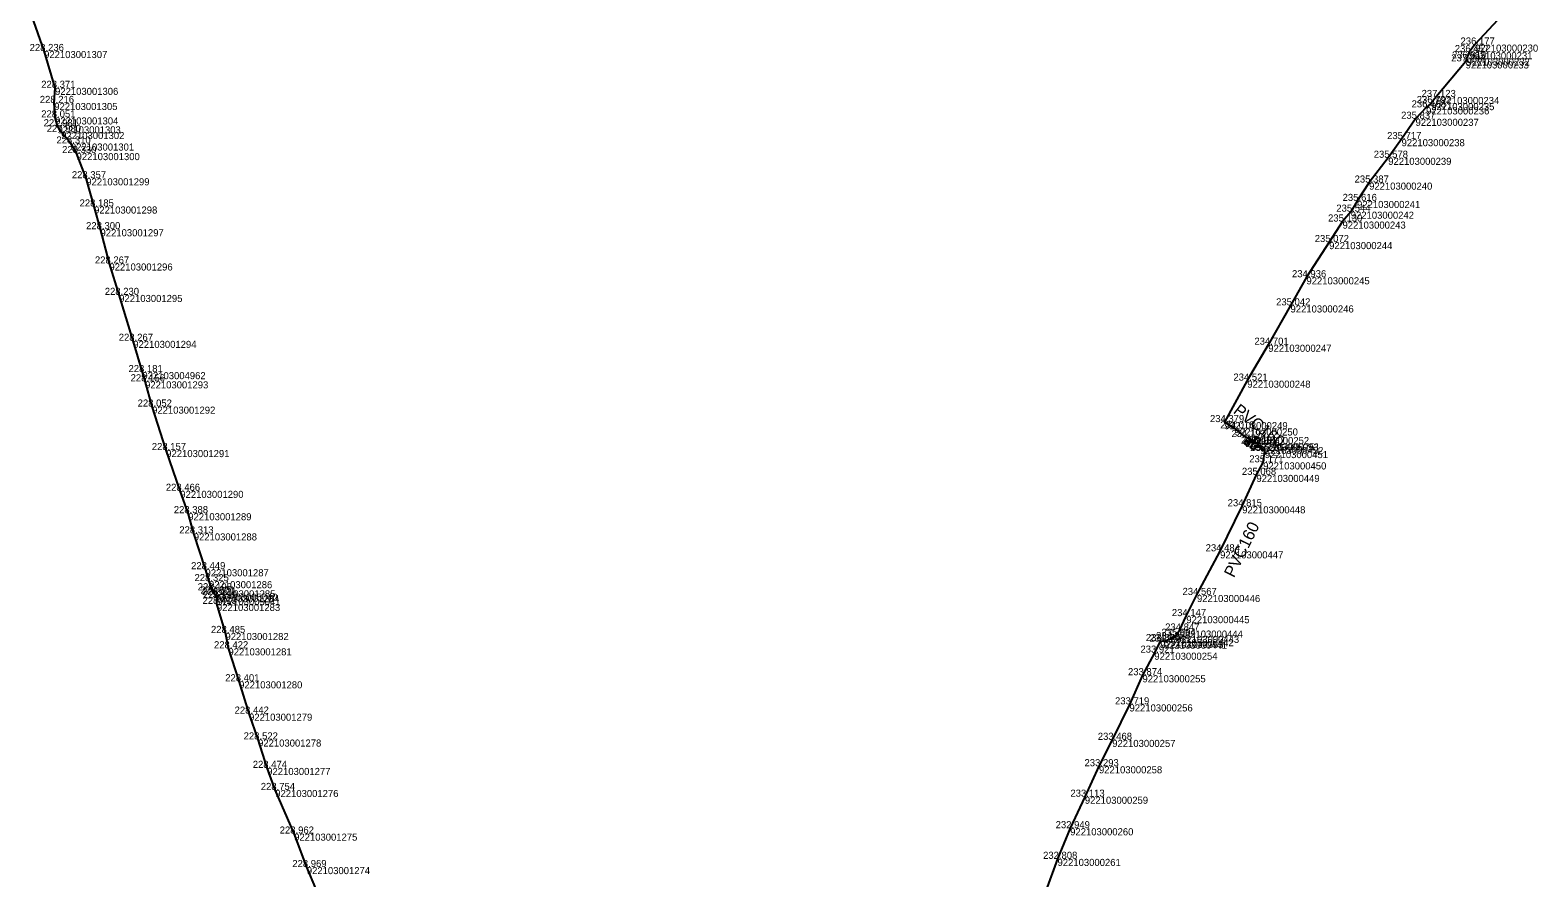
# Model space of a CAD drawing. Extents: x -771047 to -756200, y -1053876 to -1046520.
# Drawn here: x -768886.3 to -768630.8, y -1052633.5 to -1052489.9 of the extents above; entities that cross this region are included whole.
import ezdxf

# ---------------------------------------------------------------- set-up
doc = ezdxf.new("R2010")
doc.units = 0
for name, color, linetype in [('Vrstva 32', 7, 'Continuous'), ('Vrstva 33', 7, 'Continuous'), ('Vrstva 60', 7, 'Continuous'), ('Vrstva 61', 7, 'Continuous')]:
    doc.layers.add(name, color=color, linetype=linetype)

msp = doc.modelspace()

# ---------------------------------------------------------------- linework, layer by layer
at = {"layer": 'Vrstva 32'}
for points in [[(-768859.48, -1052571.73), (-768860.83, -1052567.94), (-768863.21, -1052561.03), (-768865.61, -1052553.67), (-768866.8, -1052549.39), (-768867.25, -1052547.83), (-768868.8, -1052542.53), (-768871.18, -1052534.75), (-768872.84, -1052529.43), (-768874.35, -1052523.62), (-768875.44, -1052519.77), (-768876.76, -1052514.99), (-768878.41, -1052510.72), (-768879.37, -1052509.1), (-768881.02, -1052507.15), (-768881.63, -1052506.19), (-768882.04, -1052504.68), (-768882.19, -1052502.23), (-768882.05, -1052499.67), (-768883.91, -1052493.43), (-768886.01, -1052487.46)], [(-768636.76, -1052487.33), (-768641.43, -1052492.34), (-768642.4, -1052493.62), (-768642.86, -1052494.7), (-768643.01, -1052495.19), (-768648.03, -1052501.22), (-768648.85, -1052502.25), (-768649.71, -1052502.98), (-768651.5, -1052504.91), (-768653.87, -1052508.36), (-768656.13, -1052511.52), (-768659.37, -1052515.72), (-768661.41, -1052518.83), (-768662.48, -1052520.65), (-768663.88, -1052522.32), (-768666.14, -1052525.8), (-768669.99, -1052531.76), (-768672.69, -1052536.53), (-768676.46, -1052543.19), (-768680.01, -1052549.27), (-768683.89, -1052556.3)], [(-768691.48, -1052591.61), (-768690.35, -1052589.17), (-768688.54, -1052585.58), (-768684.62, -1052578.19), (-768680.88, -1052570.56), (-768678.47, -1052565.24), (-768677.33, -1052563.12), (-768677.05, -1052561.2), (-768677.83, -1052560.51), (-768678.45, -1052559.88), (-768680.25, -1052558.83), (-768682.15, -1052557.37), (-768683.89, -1052556.3)], [(-768855.96, -1052583.24), (-768856.55, -1052581.22), (-768858.55, -1052575.15), (-768859.48, -1052571.73)], [(-768846.1, -1052614.88), (-768847.65, -1052610.06), (-768849.18, -1052605.69), (-768850.86, -1052600.21), (-768852.67, -1052594.62), (-768853.18, -1052592.02), (-768854.62, -1052587.1), (-768854.56, -1052586.13), (-768854.77, -1052585.61), (-768855.05, -1052585.35), (-768855.43, -1052584.79), (-768855.96, -1052583.24)], [(-768691.48, -1052591.61), (-768692.11, -1052592.5), (-768693.03, -1052593.06), (-768694.16, -1052593.48), (-768694.77, -1052593.39), (-768695.77, -1052595.36), (-768697.78, -1052599.18), (-768699.98, -1052604.12), (-768702.9, -1052610.13), (-768705.15, -1052614.6), (-768707.54, -1052619.76), (-768710.03, -1052625.1), (-768712.17, -1052630.29), (-768714.18, -1052635.7), (-768715.9, -1052640.84), (-768716.73, -1052643.85)], [(-768836.1, -1052638.7), (-768836.79, -1052637.16), (-768837.87, -1052635.33), (-768839.39, -1052631.68), (-768841.54, -1052626.01), (-768844.74, -1052618.62), (-768846.1, -1052614.88)]]:
    msp.add_lwpolyline(points, dxfattribs=at)
at = {"layer": 'Vrstva 33'}
for points in [[(-768678.45, -1052559.88), (-768680.25, -1052558.83), (-768682.15, -1052557.37), (-768683.89, -1052556.3)], [(-768680.37, -1052560.05), (-768680.47, -1052559.93), (-768680.46, -1052559.69), (-768680.4, -1052559.6), (-768680.2, -1052559.48), (-768680.04, -1052559.52)], [(-768680.04, -1052559.52), (-768679.6, -1052559.8)], [(-768679.27, -1052559.26), (-768679.92, -1052560.33)], [(-768679.92, -1052560.33), (-768680.37, -1052560.05)], [(-768690.35, -1052589.17), (-768688.54, -1052585.58), (-768684.62, -1052578.19), (-768680.88, -1052570.56), (-768678.47, -1052565.24), (-768677.33, -1052563.12)]]:
    msp.add_lwpolyline(points, dxfattribs=at)
msp.add_lwpolyline([(-768678.84, -1052560.98), (-768679.47, -1052560.59), (-768678.42, -1052558.88), (-768677.79, -1052559.27)], close=True, dxfattribs=at)
at = {"layer": 'Vrstva 60'}
for p, q in [((-768641.43, -1052492.34), (-768641.43, -1052492.34)), ((-768883.91, -1052493.43), (-768883.91, -1052493.43)), ((-768643.01, -1052495.19), (-768643.01, -1052495.19)), ((-768642.86, -1052494.7), (-768642.86, -1052494.7)), ((-768642.4, -1052493.62), (-768642.4, -1052493.62)), ((-768882.05, -1052499.67), (-768882.05, -1052499.67)), ((-768882.19, -1052502.23), (-768882.19, -1052502.23)), ((-768649.71, -1052502.98), (-768649.71, -1052502.98)), ((-768648.85, -1052502.25), (-768648.85, -1052502.25)), ((-768648.03, -1052501.22), (-768648.03, -1052501.22)), ((-768882.04, -1052504.68), (-768882.04, -1052504.68)), ((-768651.5, -1052504.91), (-768651.5, -1052504.91)), ((-768881.63, -1052506.19), (-768881.63, -1052506.19)), ((-768881.02, -1052507.15), (-768881.02, -1052507.15)), ((-768653.87, -1052508.36), (-768653.87, -1052508.36)), ((-768879.37, -1052509.1), (-768879.37, -1052509.1)), ((-768878.41, -1052510.72), (-768878.41, -1052510.72)), ((-768656.13, -1052511.52), (-768656.13, -1052511.52)), ((-768876.76, -1052514.99), (-768876.76, -1052514.99)), ((-768659.37, -1052515.72), (-768659.37, -1052515.72)), ((-768661.41, -1052518.83), (-768661.41, -1052518.83)), ((-768875.44, -1052519.77), (-768875.44, -1052519.77)), ((-768662.48, -1052520.65), (-768662.48, -1052520.65)), ((-768874.35, -1052523.62), (-768874.35, -1052523.62)), ((-768663.88, -1052522.32), (-768663.88, -1052522.32)), ((-768666.14, -1052525.8), (-768666.14, -1052525.8)), ((-768872.84, -1052529.43), (-768872.84, -1052529.43)), ((-768669.99, -1052531.76), (-768669.99, -1052531.76)), ((-768871.18, -1052534.75), (-768871.18, -1052534.75)), ((-768672.69, -1052536.53), (-768672.69, -1052536.53)), ((-768868.8, -1052542.53), (-768868.8, -1052542.53)), ((-768676.46, -1052543.19), (-768676.46, -1052543.19)), ((-768867.25, -1052547.83), (-768867.25, -1052547.83)), ((-768866.8, -1052549.39), (-768866.8, -1052549.39)), ((-768680.01, -1052549.27), (-768680.01, -1052549.27)), ((-768865.61, -1052553.67), (-768865.61, -1052553.67)), ((-768683.89, -1052556.3), (-768683.89, -1052556.3)), ((-768682.15, -1052557.37), (-768682.15, -1052557.37)), ((-768680.25, -1052558.83), (-768680.25, -1052558.83)), ((-768863.21, -1052561.03), (-768863.21, -1052561.03)), ((-768678.63, -1052559.93), (-768678.63, -1052559.93)), ((-768678.45, -1052559.88), (-768678.45, -1052559.88)), ((-768677.83, -1052560.51), (-768677.83, -1052560.51)), ((-768677.05, -1052561.2), (-768677.05, -1052561.2)), ((-768677.33, -1052563.12), (-768677.33, -1052563.12)), ((-768678.47, -1052565.24), (-768678.47, -1052565.24)), ((-768860.83, -1052567.94), (-768860.83, -1052567.94)), ((-768859.48, -1052571.73), (-768859.48, -1052571.73)), ((-768680.88, -1052570.56), (-768680.88, -1052570.56)), ((-768858.55, -1052575.15), (-768858.55, -1052575.15)), ((-768684.62, -1052578.19), (-768684.62, -1052578.19)), ((-768856.55, -1052581.22), (-768856.55, -1052581.22)), ((-768855.96, -1052583.24), (-768855.96, -1052583.24)), ((-768855.43, -1052584.79), (-768855.43, -1052584.79)), ((-768855.05, -1052585.35), (-768855.05, -1052585.35)), ((-768854.77, -1052585.61), (-768854.77, -1052585.61)), ((-768854.62, -1052587.1), (-768854.62, -1052587.1)), ((-768854.56, -1052586.13), (-768854.56, -1052586.13)), ((-768688.54, -1052585.58), (-768688.54, -1052585.58)), ((-768690.35, -1052589.17), (-768690.35, -1052589.17)), ((-768853.18, -1052592.02), (-768853.18, -1052592.02)), ((-768692.11, -1052592.5), (-768692.11, -1052592.5)), ((-768691.48, -1052591.61), (-768691.48, -1052591.61)), ((-768852.67, -1052594.62), (-768852.67, -1052594.62)), ((-768695.77, -1052595.36), (-768695.77, -1052595.36)), ((-768694.77, -1052593.39), (-768694.77, -1052593.39)), ((-768694.16, -1052593.48), (-768694.16, -1052593.48)), ((-768693.03, -1052593.06), (-768693.03, -1052593.06)), ((-768850.86, -1052600.21), (-768850.86, -1052600.21)), ((-768697.78, -1052599.18), (-768697.78, -1052599.18)), ((-768849.18, -1052605.69), (-768849.18, -1052605.69)), ((-768699.98, -1052604.12), (-768699.98, -1052604.12)), ((-768847.65, -1052610.06), (-768847.65, -1052610.06)), ((-768702.9, -1052610.13), (-768702.9, -1052610.13)), ((-768846.1, -1052614.88), (-768846.1, -1052614.88)), ((-768705.15, -1052614.6), (-768705.15, -1052614.6)), ((-768844.74, -1052618.62), (-768844.74, -1052618.62)), ((-768707.54, -1052619.76), (-768707.54, -1052619.76)), ((-768841.54, -1052626.01), (-768841.54, -1052626.01)), ((-768710.03, -1052625.1), (-768710.03, -1052625.1)), ((-768712.17, -1052630.29), (-768712.17, -1052630.29)), ((-768839.39, -1052631.68), (-768839.39, -1052631.68))]:
    msp.add_line(p, q, dxfattribs=at)

# ---------------------------------------------------------------- texts
at = {"layer": 'Vrstva 33'}
for rotation, p in [(322.2959, (-768682.52, -1052554.64)), (63.899, (-768682.27, -1052582.78))]:
    msp.add_text('PVC160', height=2, rotation=rotation, dxfattribs=at).set_placement(p)
at = {"layer": 'Vrstva 60'}
for s, p in [('922103000230', (-768641.43, -1052493.54)), ('922103001307', (-768883.91, -1052494.63)), ('922103000233', (-768643.01, -1052496.39)), ('922103000232', (-768642.86, -1052495.9)), ('922103000231', (-768642.4, -1052494.82)), ('922103001306', (-768882.05, -1052500.87)), ('922103001305', (-768882.19, -1052503.43)), ('922103000236', (-768649.71, -1052504.18)), ('922103000235', (-768648.85, -1052503.45)), ('922103000234', (-768648.03, -1052502.42)), ('922103001304', (-768882.04, -1052505.88)), ('922103000237', (-768651.5, -1052506.11)), ('922103001303', (-768881.63, -1052507.39)), ('922103001302', (-768881.02, -1052508.35)), ('922103000238', (-768653.87, -1052509.56)), ('922103001301', (-768879.37, -1052510.3)), ('922103001300', (-768878.41, -1052511.92)), ('922103000239', (-768656.13, -1052512.72)), ('922103001299', (-768876.76, -1052516.19)), ('922103000240', (-768659.37, -1052516.92)), ('922103000241', (-768661.41, -1052520.03)), ('922103001298', (-768875.44, -1052520.97)), ('922103000242', (-768662.48, -1052521.85)), ('922103001297', (-768874.35, -1052524.82)), ('922103000243', (-768663.88, -1052523.52)), ('922103000244', (-768666.14, -1052527)), ('922103001296', (-768872.84, -1052530.62)), ('922103000245', (-768669.99, -1052532.96)), ('922103001295', (-768871.18, -1052535.95)), ('922103000246', (-768672.69, -1052537.73)), ('922103001294', (-768868.8, -1052543.73)), ('922103000247', (-768676.46, -1052544.39)), ('922103004962', (-768867.25, -1052549.03)), ('922103001293', (-768866.8, -1052550.59)), ('922103000248', (-768680.01, -1052550.47)), ('922103001292', (-768865.61, -1052554.87)), ('922103000249', (-768683.89, -1052557.5)), ('922103000250', (-768682.15, -1052558.57)), ('922103000252', (-768680.25, -1052560.03)), ('922103001291', (-768863.21, -1052562.23)), ('922103005093', (-768678.63, -1052561.13)), ('922103000251', (-768678.45, -1052561.08)), ('922103000452', (-768677.83, -1052561.71)), ('922103000451', (-768677.05, -1052562.4)), ('922103000450', (-768677.33, -1052564.32)), ('922103000449', (-768678.47, -1052566.44)), ('922103001290', (-768860.83, -1052569.14)), ('922103001289', (-768859.48, -1052572.93)), ('922103000448', (-768680.88, -1052571.76)), ('922103001288', (-768858.55, -1052576.35)), ('922103000447', (-768684.62, -1052579.39)), ('922103001287', (-768856.55, -1052582.42)), ('922103001286', (-768855.96, -1052584.44)), ('922103001285', (-768855.43, -1052585.99)), ('922103005040', (-768855.05, -1052586.55)), ('922103001284', (-768854.77, -1052586.81)), ('922103001283', (-768854.62, -1052588.3)), ('922103005041', (-768854.56, -1052587.33)), ('922103000446', (-768688.54, -1052586.78)), ('922103000445', (-768690.35, -1052590.37)), ('922103001282', (-768853.18, -1052593.22)), ('922103000443', (-768692.11, -1052593.7)), ('922103000444', (-768691.48, -1052592.81)), ('922103001281', (-768852.67, -1052595.82)), ('922103000254', (-768695.77, -1052596.56)), ('922103000253', (-768694.77, -1052594.59)), ('922103000441', (-768694.16, -1052594.68)), ('922103000442', (-768693.03, -1052594.26)), ('922103001280', (-768850.86, -1052601.41)), ('922103000255', (-768697.78, -1052600.38)), ('922103001279', (-768849.18, -1052606.89)), ('922103000256', (-768699.98, -1052605.32)), ('922103001278', (-768847.65, -1052611.27)), ('922103000257', (-768702.9, -1052611.33)), ('922103001277', (-768846.1, -1052616.08)), ('922103000258', (-768705.15, -1052615.8)), ('922103001276', (-768844.74, -1052619.82)), ('922103000259', (-768707.54, -1052620.96)), ('922103001275', (-768841.54, -1052627.21)), ('922103000260', (-768710.03, -1052626.3)), ('922103000261', (-768712.17, -1052631.49)), ('922103001274', (-768839.39, -1052632.88))]:
    msp.add_text(s, height=1.2, dxfattribs=at).set_placement(p)
at = {"layer": 'Vrstva 61'}
for s, p in [('228.236', (-768886.36, -1052493.43)), ('236.457', (-768644.85, -1052493.62)), ('236.177', (-768643.88, -1052492.34)), ('237.292', (-768645.46, -1052495.19)), ('236.919', (-768645.32, -1052494.7)), ('228.371', (-768884.4, -1052499.67)), ('237.123', (-768650.48, -1052501.22)), ('228.216', (-768884.64, -1052502.23)), ('228.051', (-768884.4, -1052504.68)), ('236.468', (-768652.17, -1052502.98)), ('236.792', (-768651.3, -1052502.25)), ('227.981', (-768883.99, -1052506.19)), ('227.980', (-768883.47, -1052507.15)), ('235.837', (-768653.95, -1052504.91)), ('228.310', (-768881.82, -1052509.1)), ('235.717', (-768656.32, -1052508.36)), ('228.330', (-768880.86, -1052510.72)), ('235.578', (-768658.59, -1052511.52)), ('228.357', (-768879.21, -1052514.99)), ('235.387', (-768661.83, -1052515.72)), ('228.185', (-768877.9, -1052519.77)), ('235.616', (-768663.86, -1052518.83)), ('235.130', (-768666.33, -1052522.32)), ('235.544', (-768664.93, -1052520.65)), ('228.300', (-768876.8, -1052523.62)), ('235.072', (-768668.59, -1052525.8)), ('228.267', (-768875.3, -1052529.43)), ('234.936', (-768672.44, -1052531.76)), ('228.230', (-768873.63, -1052534.75)), ('235.042', (-768675.13, -1052536.53)), ('228.267', (-768871.26, -1052542.53)), ('234.701', (-768678.81, -1052543.19)), ('228.181', (-768869.61, -1052547.83)), ('228.156', (-768869.25, -1052549.39)), ('234.521', (-768682.37, -1052549.27)), ('228.052', (-768868.06, -1052553.67)), ('234.379', (-768686.34, -1052556.3)), ('234.018', (-768684.6, -1052557.37)), ('234.193', (-768682.7, -1052558.83)), ('236.110', (-768681.08, -1052559.93)), ('235.491', (-768680.8, -1052559.88)), ('235.206', (-768680.29, -1052560.51)), ('228.157', (-768865.66, -1052561.03)), ('235.171', (-768679.68, -1052563.12)), ('235.285', (-768679.51, -1052561.2)), ('235.068', (-768680.93, -1052565.24)), ('228.466', (-768863.28, -1052567.94)), ('234.815', (-768683.34, -1052570.56)), ('228.388', (-768861.93, -1052571.73)), ('228.313', (-768861, -1052575.15)), ('234.484', (-768687.07, -1052578.19)), ('228.449', (-768859, -1052581.22)), ('228.325', (-768858.42, -1052583.24)), ('228.198', (-768857.88, -1052584.79)), ('228.801', (-768857.41, -1052585.35)), ('228.121', (-768857.13, -1052585.61)), ('228.119', (-768857.01, -1052586.13)), ('234.567', (-768690.99, -1052585.58)), ('228.413', (-768857.07, -1052587.1)), ('234.847', (-768693.93, -1052591.61)), ('234.147', (-768692.8, -1052589.17)), ('228.485', (-768855.63, -1052592.02)), ('233.870', (-768697.22, -1052593.39)), ('234.347', (-768696.61, -1052593.48)), ('234.856', (-768695.48, -1052593.06)), ('235.004', (-768694.56, -1052592.5)), ('228.422', (-768855.12, -1052594.62)), ('233.921', (-768698.12, -1052595.36)), ('233.874', (-768700.23, -1052599.18)), ('228.401', (-768853.22, -1052600.21)), ('233.719', (-768702.43, -1052604.12)), ('228.442', (-768851.63, -1052605.69)), ('228.522', (-768850.1, -1052610.06)), ('233.468', (-768705.35, -1052610.13)), ('233.293', (-768707.6, -1052614.6)), ('228.474', (-768848.55, -1052614.88)), ('228.754', (-768847.19, -1052618.62)), ('233.113', (-768709.99, -1052619.76)), ('228.962', (-768843.99, -1052626.01)), ('232.949', (-768712.49, -1052625.1)), ('228.969', (-768841.85, -1052631.68)), ('232.808', (-768714.62, -1052630.29))]:
    msp.add_text(s, height=1.2, dxfattribs=at).set_placement(p)

doc.saveas('drawing.dxf')
